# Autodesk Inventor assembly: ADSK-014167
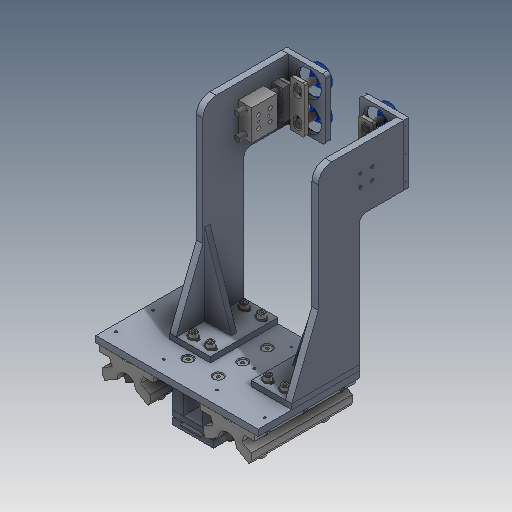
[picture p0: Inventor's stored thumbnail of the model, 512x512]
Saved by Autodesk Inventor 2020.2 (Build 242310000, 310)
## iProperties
Created: 2019-10
Part Number: ADSK-014167
Document SubType Name: Assembly
Designer: lutzd
Mass: 11336.3 g
Surface Area: 8734.65 cm^2
Volume: 3966.53 cm^3
Density: 2.85799 g/cm^3
VLDS_Profile: Default Assembly
VLDS_TimeStamp: 2016-07-29
VLDS_FailCnt: 0
VLDS_AcceptCnt: 0
Dimensions: 297,2x469x305 mm
Mass: 11,336 kg
DocNumber: ADSK-014167
Folder: 01 - Themengebiete\Simplification\01 - Packaging machine\
VDS_Category: 3D Komponenten
VDS_NumSchm: Autodesk
Title: guideline complete
Author: lutzd
Revision Number: -
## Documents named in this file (23)
- D:\07 - DEMODATEN\OTX 2019 - Dataset - UPDATE - Dez2019\Designs\07-Packing machine\ADSK-014167.iam
- D:\07 - DEMODATEN\OTX 2019 - Dataset - UPDATE - Dez2019\Designs\07-Packing machine\500204R.iam
- D:\07 - DEMODATEN\OTX 2019 - Dataset - UPDATE - Dez2019\Designs\07-Packing machine\Parts\ADSK-011357.ipt
- D:\07 - DEMODATEN\OTX 2019 - Dataset - UPDATE - Dez2019\Designs\07-Packing machine\Parts\ADSK-011356.ipt
- D:\07 - DEMODATEN\OTX 2019 - Dataset - UPDATE - Dez2019\Designs\07-Packing machine\Parts\ADSK-011759.ipt
- D:\07 - DEMODATEN\OTX 2019 - Dataset - UPDATE - Dez2019\Content Center Files\de-DE\ISO 4762(2)\ISO 4762 - M8 x 16ISO.ipt
- D:\07 - DEMODATEN\OTX 2019 - Dataset - UPDATE - Dez2019\Content Center Files\de-DE\ISO 10642(1)\ISO 10642 - M8x25.ipt
- D:\07 - DEMODATEN\OTX 2019 - Dataset - UPDATE - Dez2019\Designs\07-Packing machine\Parts\ADSK-011763.ipt
- D:\07 - DEMODATEN\OTX 2019 - Dataset - UPDATE - Dez2019\Content Center Files\de-DE\DIN 9021\DIN 9021 - 4,3.ipt
- D:\07 - DEMODATEN\OTX 2019 - Dataset - UPDATE - Dez2019\Content Center Files\de-DE\ISO 4762(2)\ISO 4762 - M4 x 20ISO.ipt
- D:\07 - DEMODATEN\OTX 2019 - Dataset - UPDATE - Dez2019\Designs\07-Packing machine\500201L.iam
- D:\07 - DEMODATEN\OTX 2019 - Dataset - UPDATE - Dez2019\Designs\07-Packing machine\500201R.iam
- D:\07 - DEMODATEN\OTX 2019 - Dataset - UPDATE - Dez2019\Content Center Files\de-DE\DIN 125-1  B\DIN 125-1 - B 8,4.ipt
- D:\07 - DEMODATEN\OTX 2019 - Dataset - UPDATE - Dez2019\Content Center Files\de-DE\ISO 4762(2)\ISO 4762 - M8 x 20ISO.ipt
- D:\07 - DEMODATEN\OTX 2019 - Dataset - UPDATE - Dez2019\Designs\07-Packing machine\Parts\ADSK-011295.ipt
- D:\07 - DEMODATEN\OTX 2019 - Dataset - UPDATE - Dez2019\Content Center Files\de-DE\ISO 4762(2)\ISO 4762 - M5 x 12ISO.ipt
- D:\07 - DEMODATEN\OTX 2019 - Dataset - UPDATE - Dez2019\Designs\07-Packing machine\A105050.iam
- D:\07 - DEMODATEN\OTX 2019 - Dataset - UPDATE - Dez2019\Designs\07-Packing machine\Parts\ADSK-011311.ipt
- D:\07 - DEMODATEN\OTX 2019 - Dataset - UPDATE - Dez2019\Designs\07-Packing machine\Parts\ADSK-011788.ipt
- D:\07 - DEMODATEN\OTX 2019 - Dataset - UPDATE - Dez2019\Designs\07-Packing machine\Parts\ADSK-011375.ipt
- D:\07 - DEMODATEN\OTX 2019 - Dataset - UPDATE - Dez2019\Content Center Files\de-DE\ISO 4762(2)\ISO 4762 - M3 x 16ISO.ipt
- D:\07 - DEMODATEN\OTX 2019 - Dataset - UPDATE - Dez2019\Designs\07-Packing machine\Parts\ADSK-011358.ipt
- D:\07 - DEMODATEN\OTX 2019 - Dataset - UPDATE - Dez2019\Content Center Files\de-DE\ISO 10642(1)\ISO 10642 - M8x20.ipt
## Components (96 placed, 22 different names)
1. 500204R:1 [sub-assembly] — Passend:1, Passend:2, Passend:3, Passend:4, Passend:5, Passend:6, Passend:20, Fluchtend:1, Passend:21, Passend:22, Passend:23, Passend:24, Passend:25, Passend:31, Passend:32, Passend:56, Passend:57, Passend:58, Passend:59, Passend:60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
2. ADSK-011357:1 — Passend:1, Passend:2, Passend:3, Passend:11, Passend:12, Passend:120, Passend:122, Passend:123
3. ADSK-011357:2 — Passend:4, Passend:5, Passend:6
4. ADSK-011356:1 — Passend:10, Passend:11, Passend:12, Passend:128
5. ADSK-011759:1
6. ADSK-011763:1 — Passend:20, Passend:22, Passend:23, Passend:65, Passend:66, Passend:67, Passend:68, Passend:69, Passend:70
7. ADSK-011763:2 — Fluchtend:1, Passend:21, Passend:24, Passend:28, Passend:33, Passend:34, Passend:37, Passend:71, Passend:72, Passend:73
8. 500201L:1 [sub-assembly] — Passend:74, Passend:75, Passend:76, Passend:91, Passend:92, Passend:93, Passend:94, Passend:98, Passend:102, Passend:103, Passend:104, Passend:108, Passend:109
9. 500201R:1 [sub-assembly] — Passend:77, Passend:78, Passend:79, Passend:95, Passend:96, Passend:97, Passend:99, Passend:100, Passend:101, Passend:105, Passend:106, Passend:107
10. ADSK-011295:1 — Passend:98, Passend:102, Passend:103, Passend:118, Passend:119
11. ADSK-011295:2 — Passend:99, Passend:100, Passend:101, Passend:116, Passend:117
12. A105050:1 [sub-assembly] — Passend:104, Passend:108, Passend:109, Passend:110, Passend:111, Passend:112
13. A105050:2 [sub-assembly] — Passend:105, Passend:106, Passend:107, Passend:113, Passend:114, Passend:115
14. ADSK-011311:1 — Passend:113, Passend:114, Passend:115, Fluchtend:2, Fluchtend:3, Fluchtend:6
15. ADSK-011311:2 — Passend:110, Passend:111, Passend:112, Fluchtend:4, Fluchtend:5, Fluchtend:6
16. ADSK-011788:1
17. ADSK-011375:1 — Passend:116, Fluchtend:2
18. ADSK-011788:2
19. ADSK-011375:2 — Passend:117, Fluchtend:3
20. ADSK-011788:3
21. ADSK-011375:3 — Passend:118, Fluchtend:5
22. ADSK-011788:4
23. ADSK-011375:4 — Passend:119, Fluchtend:4
24. ADSK-011358:1 — Passend:120, Passend:121, Passend:122, Passend:123, Passend:124, Passend:125, Passend:126, Passend:127, Passend:128
25. ISO 10642 M8x20:1 — Passend:124
26. ISO 10642 M8x20:2 — Passend:126
27. ISO 10642 M8x20:3 — Passend:127
28. ISO 10642 M8x20:4 — Passend:125
29. ISO 4762 M3 x 16:1
30. ISO 4762 M3 x 16:2
31. ISO 4762 M3 x 16:3
32. ISO 4762 M3 x 16:4
33. ISO 4762 M3 x 16:5
34. ISO 4762 M3 x 16:6
35. ISO 4762 M3 x 16:7
36. ISO 4762 M3 x 16:8
37. ISO 4762 M5 x 12:1
38. ISO 4762 M5 x 12:2
39. ISO 4762 M5 x 12:3
40. ISO 4762 M5 x 12:4
41. ISO 4762 M5 x 12:5
42. ISO 4762 M5 x 12:6
43. DIN 125-1 B B 8,4:1
44. ISO 4762 M8 x 20:1
45. ISO 4762 M8 x 20:2 — Einfügen:11, Passend:85
46. DIN 125-1 B B 8,4:2 — Einfügen:11, Passend:97
47. ISO 4762 M8 x 20:3 — Passend:87
48. DIN 125-1 B B 8,4:3 — Passend:93
49. ISO 4762 M8 x 20:4 — Passend:90
50. DIN 125-1 B B 8,4:4 — Passend:92
51. ISO 4762 M8 x 20:5 — Passend:89
52. DIN 125-1 B B 8,4:5 — Passend:91
53. ISO 4762 M8 x 20:6 — Passend:88
54. DIN 125-1 B B 8,4:6 — Passend:94
55. ISO 4762 M8 x 20:7 — Passend:86
56. DIN 125-1 B B 8,4:7 — Passend:95
57. ISO 4762 M8 x 20:8 — Passend:84
58. DIN 125-1 B B 8,4:8 — Passend:96
59. ISO 4762 M8 x 16:1
60. ISO 4762 M8 x 16:2
61. ISO 4762 M8 x 16:3
62. ISO 4762 M8 x 16:4
63. ISO 4762 M8 x 16:5
64. ISO 4762 M8 x 16:6
65. ISO 4762 M8 x 16:7
66. ISO 4762 M8 x 16:8
67. ISO 10642 M8x25:1
68. ISO 10642 M8x25:2
69. ISO 10642 M8x25:3
70. ISO 10642 M8x25:4
71. ISO 10642 M8x25:5
72. ISO 10642 M8x25:6
73. DIN 9021 4,3:3 — Passend:25, Passend:27, Passend:28
74. ISO 4762 M4 x 20:1 — Passend:27
75. DIN 9021 4,3:4 — Einfügen:10, Passend:33
76. ISO 4762 M4 x 20:2 — Passend:31, Einfügen:10
77. DIN 9021 4,3:5 — Passend:34, Passend:35, Passend:36, Passend:37
78. ISO 4762 M4 x 20:3 — Passend:32, Passend:35, Passend:36
79. DIN 9021 4,3:6 — Passend:72
80. ISO 4762 M4 x 20:4 — Passend:57
81. DIN 9021 4,3:7 — Passend:73
82. ISO 4762 M4 x 20:5 — Passend:58
83. DIN 9021 4,3:8 — Passend:71
84. ISO 4762 M4 x 20:6 — Passend:56
85. DIN 9021 4,3:9 — Passend:68
86. ISO 4762 M4 x 20:7 — Passend:59
87. DIN 9021 4,3:10 — Passend:69
88. ISO 4762 M4 x 20:8 — Passend:60
89. DIN 9021 4,3:11 — Passend:70
90. ISO 4762 M4 x 20:9 — Passend:61
91. DIN 9021 4,3:12 — Passend:65
92. ISO 4762 M4 x 20:10 — Passend:64
93. DIN 9021 4,3:13 — Passend:66
94. ISO 4762 M4 x 20:11 — Passend:63
95. DIN 9021 4,3:14 — Passend:67
96. ISO 4762 M4 x 20:12 — Passend:62
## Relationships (101: Mate 93, Flush 6, Insert 2)
- Passend:1 [Mate]: 500204R:1 ↔ ADSK-011357:1
- Passend:2 [Mate]: 500204R:1 ↔ ADSK-011357:1
- Passend:3 [Mate]: 500204R:1 ↔ ADSK-011357:1
- Passend:4 [Mate]: 500204R:1 ↔ ADSK-011357:2
- Passend:5 [Mate]: 500204R:1 ↔ ADSK-011357:2
- Passend:6 [Mate]: 500204R:1 ↔ ADSK-011357:2
- Passend:10 [Mate]: ADSK-011356:1
- Passend:11 [Mate]: ADSK-011357:1 ↔ ADSK-011356:1
- Passend:12 [Mate]: ADSK-011357:1 ↔ ADSK-011356:1
- Passend:20 [Mate]: 500204R:1 ↔ ADSK-011763:1
- Fluchtend:1 [Flush]: 500204R:1 ↔ ADSK-011763:2
- Passend:21 [Mate]: 500204R:1 ↔ ADSK-011763:2
- Passend:22 [Mate]: 500204R:1 ↔ ADSK-011763:1
- Passend:23 [Mate]: 500204R:1 ↔ ADSK-011763:1
- Passend:24 [Mate]: 500204R:1 ↔ ADSK-011763:2
- Passend:25 [Mate]: 500204R:1 ↔ DIN 9021 4,3:3
- Passend:27 [Mate]: DIN 9021 4,3:3 ↔ ISO 4762 M4 x 20:1
- Passend:28 [Mate]: ADSK-011763:2 ↔ DIN 9021 4,3:3
- Passend:31 [Mate]: 500204R:1 ↔ ISO 4762 M4 x 20:2
- Passend:32 [Mate]: 500204R:1 ↔ ISO 4762 M4 x 20:3
- Einfügen:10 [Insert]: DIN 9021 4,3:4 ↔ ISO 4762 M4 x 20:2
- Passend:33 [Mate]: ADSK-011763:2 ↔ DIN 9021 4,3:4
- Passend:34 [Mate]: ADSK-011763:2 ↔ DIN 9021 4,3:5
- Passend:35 [Mate]: DIN 9021 4,3:5 ↔ ISO 4762 M4 x 20:3
- Passend:36 [Mate]: DIN 9021 4,3:5 ↔ ISO 4762 M4 x 20:3
- Passend:37 [Mate]: ADSK-011763:2 ↔ DIN 9021 4,3:5
- Passend:56 [Mate]: 500204R:1 ↔ ISO 4762 M4 x 20:6
- Passend:57 [Mate]: 500204R:1 ↔ ISO 4762 M4 x 20:4
- Passend:58 [Mate]: 500204R:1 ↔ ISO 4762 M4 x 20:5
- Passend:59 [Mate]: 500204R:1 ↔ ISO 4762 M4 x 20:7
- Passend:60 [Mate]: 500204R:1 ↔ ISO 4762 M4 x 20:8
- Passend:61 [Mate]: 500204R:1 ↔ ISO 4762 M4 x 20:9
- Passend:62 [Mate]: 500204R:1 ↔ ISO 4762 M4 x 20:12
- Passend:63 [Mate]: 500204R:1 ↔ ISO 4762 M4 x 20:11
- Passend:64 [Mate]: 500204R:1 ↔ ISO 4762 M4 x 20:10
- Passend:65 [Mate]: ADSK-011763:1 ↔ DIN 9021 4,3:12
- Passend:66 [Mate]: ADSK-011763:1 ↔ DIN 9021 4,3:13
- Passend:67 [Mate]: ADSK-011763:1 ↔ DIN 9021 4,3:14
- Passend:68 [Mate]: ADSK-011763:1 ↔ DIN 9021 4,3:9
- Passend:69 [Mate]: ADSK-011763:1 ↔ DIN 9021 4,3:10
- Passend:70 [Mate]: ADSK-011763:1 ↔ DIN 9021 4,3:11
- Passend:71 [Mate]: ADSK-011763:2 ↔ DIN 9021 4,3:8
- Passend:72 [Mate]: ADSK-011763:2 ↔ DIN 9021 4,3:6
- Passend:73 [Mate]: ADSK-011763:2 ↔ DIN 9021 4,3:7
- Passend:74 [Mate]: 500204R:1 ↔ 500201L:1
- Passend:75 [Mate]: 500204R:1 ↔ 500201L:1
- Passend:76 [Mate]: 500204R:1 ↔ 500201L:1
- Passend:77 [Mate]: 500204R:1 ↔ 500201R:1
- Passend:78 [Mate]: 500204R:1 ↔ 500201R:1
- Passend:79 [Mate]: 500204R:1 ↔ 500201R:1
- Einfügen:11 [Insert]: ISO 4762 M8 x 20:2 ↔ DIN 125-1 B B 8,4:2
- Passend:84 [Mate]: 500204R:1 ↔ ISO 4762 M8 x 20:8
- Passend:85 [Mate]: 500204R:1 ↔ ISO 4762 M8 x 20:2
- Passend:86 [Mate]: 500204R:1 ↔ ISO 4762 M8 x 20:7
- Passend:87 [Mate]: 500204R:1 ↔ ISO 4762 M8 x 20:3
- Passend:88 [Mate]: 500204R:1 ↔ ISO 4762 M8 x 20:6
- Passend:89 [Mate]: 500204R:1 ↔ ISO 4762 M8 x 20:5
- Passend:90 [Mate]: 500204R:1 ↔ ISO 4762 M8 x 20:4
- Passend:91 [Mate]: 500201L:1 ↔ DIN 125-1 B B 8,4:5
- Passend:92 [Mate]: 500201L:1 ↔ DIN 125-1 B B 8,4:4
- Passend:93 [Mate]: 500201L:1 ↔ DIN 125-1 B B 8,4:3
- Passend:94 [Mate]: 500201L:1 ↔ DIN 125-1 B B 8,4:6
- Passend:95 [Mate]: 500201R:1 ↔ DIN 125-1 B B 8,4:7
- Passend:96 [Mate]: 500201R:1 ↔ DIN 125-1 B B 8,4:8
- Passend:97 [Mate]: 500201R:1 ↔ DIN 125-1 B B 8,4:2
- Passend:98 [Mate]: 500201L:1 ↔ ADSK-011295:1
- Passend:99 [Mate]: 500201R:1 ↔ ADSK-011295:2
- Passend:100 [Mate]: 500201R:1 ↔ ADSK-011295:2
- Passend:101 [Mate]: 500201R:1 ↔ ADSK-011295:2
- Passend:102 [Mate]: 500201L:1 ↔ ADSK-011295:1
- Passend:103 [Mate]: 500201L:1 ↔ ADSK-011295:1
- Passend:104 [Mate]: 500201L:1 ↔ A105050:1
- Passend:105 [Mate]: 500201R:1 ↔ A105050:2
- Passend:106 [Mate]: 500201R:1 ↔ A105050:2
- Passend:107 [Mate]: 500201R:1 ↔ A105050:2
- Passend:108 [Mate]: 500201L:1 ↔ A105050:1
- Passend:109 [Mate]: 500201L:1 ↔ A105050:1
- Passend:110 [Mate]: A105050:1 ↔ ADSK-011311:2
- Passend:111 [Mate]: A105050:1 ↔ ADSK-011311:2
- Passend:112 [Mate]: A105050:1 ↔ ADSK-011311:2
- Passend:113 [Mate]: A105050:2 ↔ ADSK-011311:1
- Passend:114 [Mate]: A105050:2 ↔ ADSK-011311:1
- Passend:115 [Mate]: A105050:2 ↔ ADSK-011311:1
- Passend:116 [Mate]: ADSK-011295:2 ↔ ADSK-011375:1
- Passend:117 [Mate]: ADSK-011295:2 ↔ ADSK-011375:2
- Passend:118 [Mate]: ADSK-011295:1 ↔ ADSK-011375:3
- Passend:119 [Mate]: ADSK-011295:1 ↔ ADSK-011375:4
- Fluchtend:2 [Flush]: ADSK-011311:1 ↔ ADSK-011375:1
- Fluchtend:3 [Flush]: ADSK-011311:1 ↔ ADSK-011375:2
- Fluchtend:4 [Flush]: ADSK-011311:2 ↔ ADSK-011375:4
- Fluchtend:5 [Flush]: ADSK-011311:2 ↔ ADSK-011375:3
- Fluchtend:6 [Flush]: ADSK-011311:1 ↔ ADSK-011311:2
- Passend:120 [Mate]: ADSK-011357:1 ↔ ADSK-011358:1
- Passend:121 [Mate]: 500204R:1 ↔ ADSK-011358:1
- Passend:122 [Mate]: ADSK-011357:1 ↔ ADSK-011358:1
- Passend:123 [Mate]: ADSK-011357:1 ↔ ADSK-011358:1
- Passend:124 [Mate]: ADSK-011358:1 ↔ ISO 10642 M8x20:1
- Passend:125 [Mate]: ADSK-011358:1 ↔ ISO 10642 M8x20:4
- Passend:126 [Mate]: ADSK-011358:1 ↔ ISO 10642 M8x20:2
- Passend:127 [Mate]: ADSK-011358:1 ↔ ISO 10642 M8x20:3
- Passend:128 [Mate]: ADSK-011356:1 ↔ ADSK-011358:1
## Named parameters: d39_d37 = 0, d51_d48 = 0, d52_d49 = 0, d53_d48 = 0, d54_d49 = 0, d55_d48 = 0, d56_d49 = 0, d57_d48 = 0, d58_d49 = 0, d59_d48 = 0, d60_d49 = 0, d61_d48 = 0, d62_d49 = 0, d63_d48 = 0, d64_d49 = 0, d65_d48 = 0, d66_d49 = 0, d67_d48 = 0, d68_d49 = 0, d99_d98 = 0, d100_d98 = 0, d101_d98 = 0, d102_d98 = 0, d103_d98 = 0, d104_d98 = 0, d145_d1173 = 7.9375 mm, d146_d1173 = 7.9375 mm, d147_d1173 = 7.9375 mm
